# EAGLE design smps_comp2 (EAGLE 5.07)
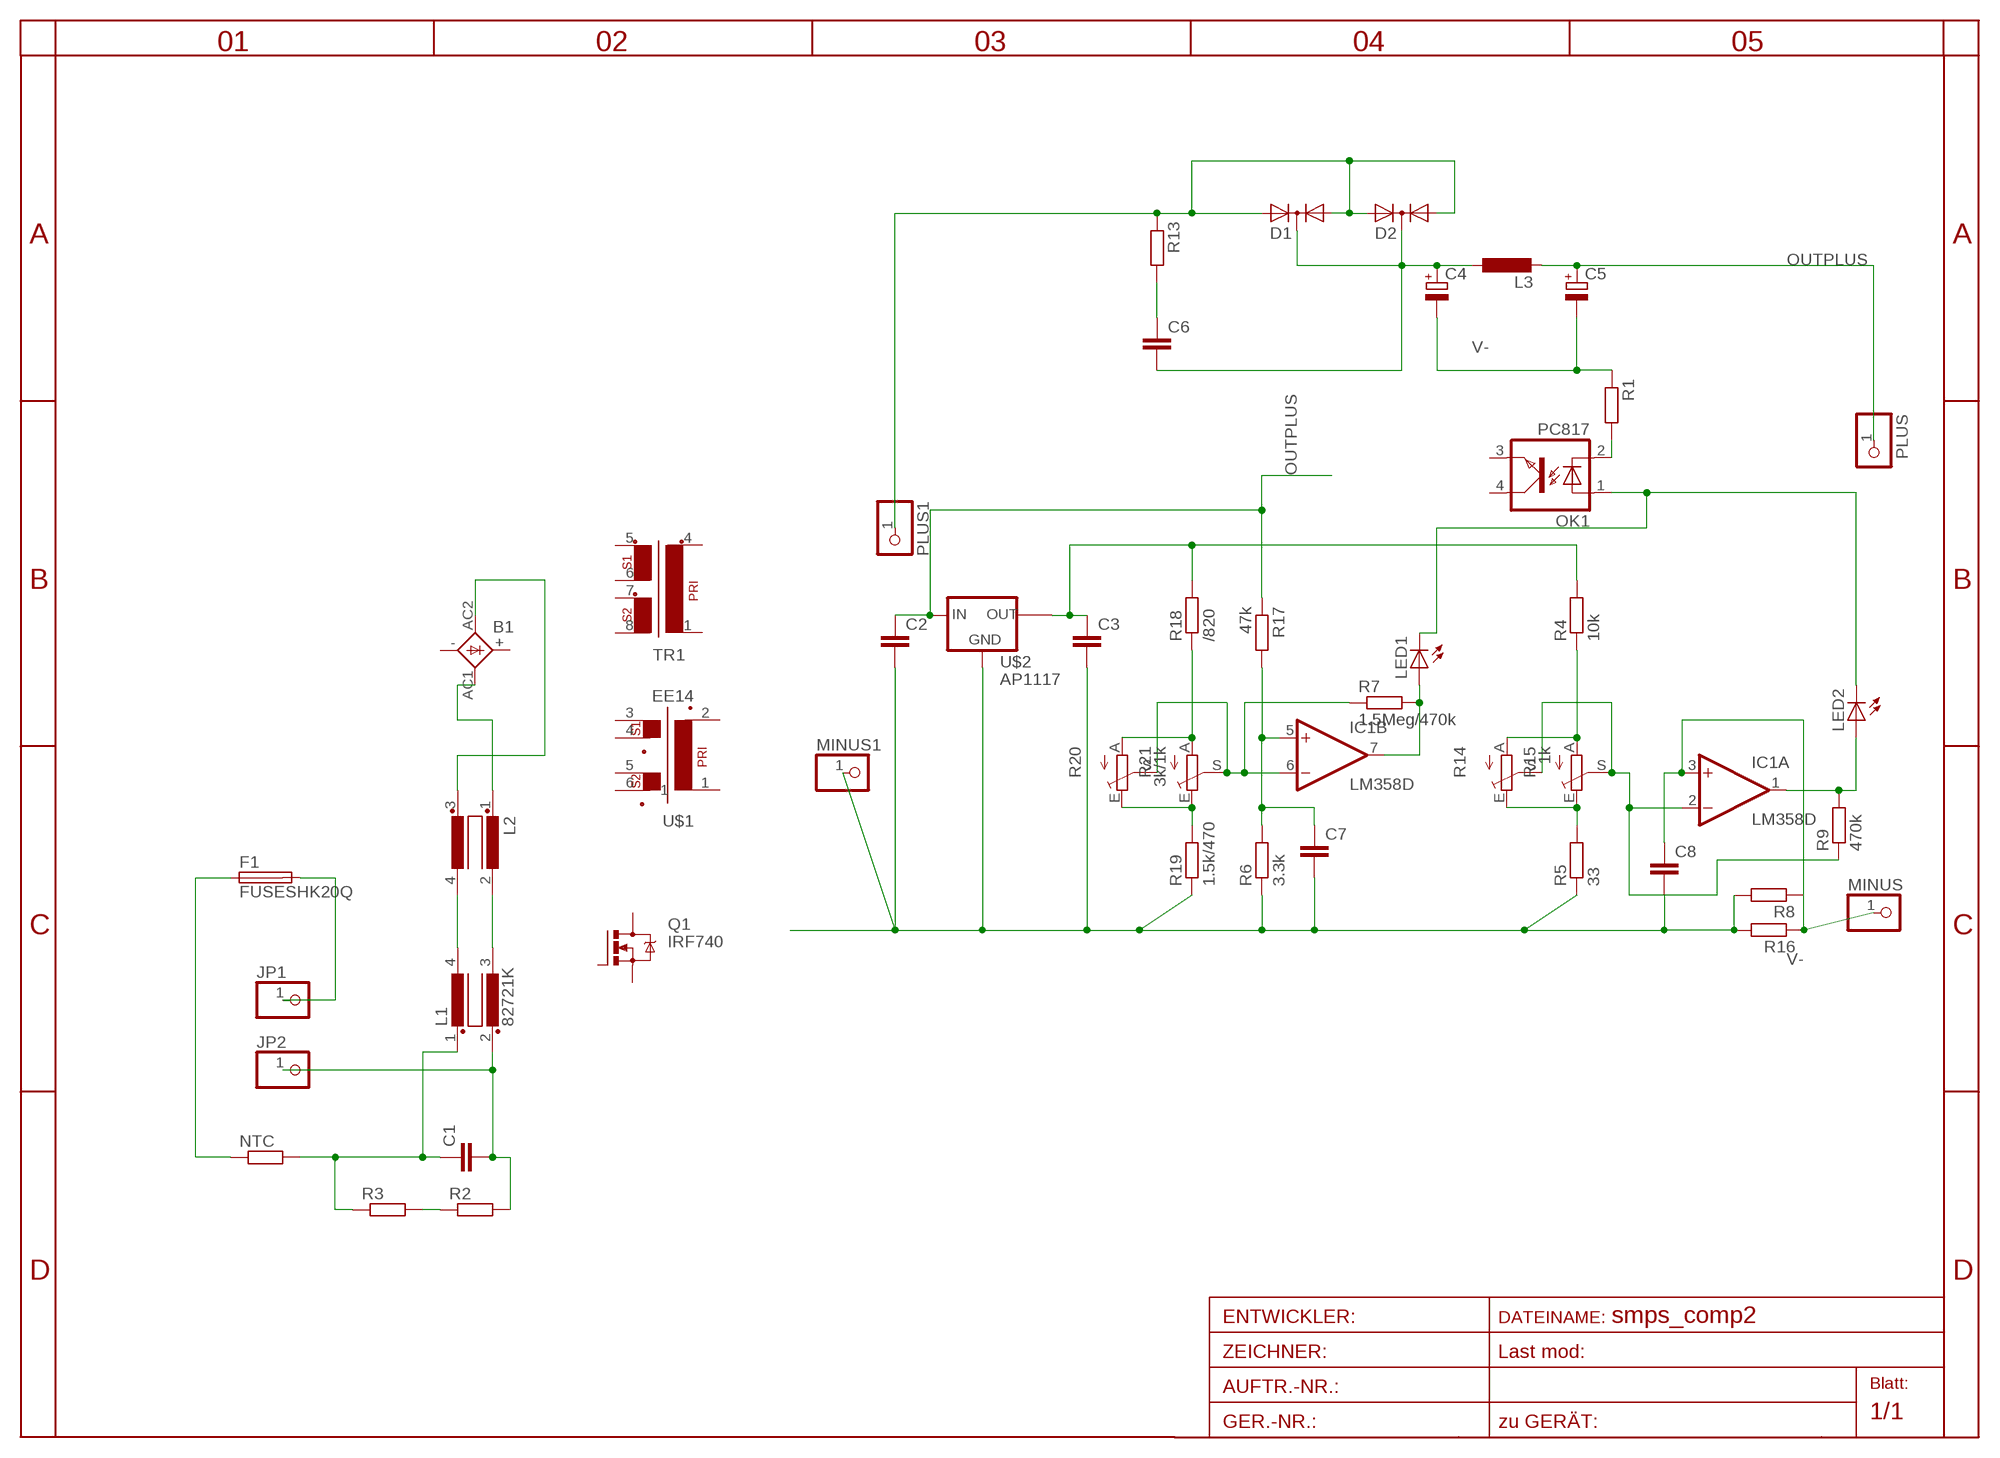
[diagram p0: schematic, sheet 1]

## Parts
B1  KBL  [KBL]
C1  C-EU150-084X183  [C150-084X183]
C2  C-EUC1206  [C1206]
C3  C-EUC1206  [C1206]
C4  CPOL-EUE5-8.5  [E5-8,5]
C5  CPOL-EUE5-8.5  [E5-8,5]
C6  C-EUC0805  [C0805]
C7  C-EUC0805  [C0805]
C8  C-EUC0805  [C0805]
D1  DIODE-2AC|CAIW220V  [IW220ABS]
D2  DIODE-2AC|CAIW220V  [IW220ABS]
F1  FUSESHK20Q  [SHK20Q]
IC1  LM358D  [SO08]
JP1  PINHD-1X12MM2  [1X2MM2]
JP2  PINHD-1X12MM2  [1X2MM2]
L1  82721K  [82721K]
L2  R1405VB1  [B1]
L3  L-EU0207/12  [0207/12]
LED1  LED3MM  [LED3MM]
LED2  LED3MM  [LED3MM]
MINUS  PINHD-1X12MM2  [1X2MM2]
MINUS1  PINHD-1X11X0.4  [1X01]
NTC  R-EU_0204/7  [0204/7]
OK1  PC817  [DIL04]
PLUS  PINHD-1X12MM2  [1X2MM2]
PLUS1  PINHD-1X11X0.4  [1X01]
Q1  IRF740  [TO220BV]
R1  R-EU_R0805  [R0805]
R2  R-EU_R1206  [R1206]
R3  R-EU_R1206  [R1206]
R4  10k  R-EU_R1206  [R1206]
R5  33  R-EU_R0805  [R0805]
R6  3.3k  R-EU_R0805  [R0805]
R7  1.5Meg/470k  R-EU_R0805  [R0805]
R8  R-EU_R2010  [R2010]
R9  470k  R-EU_R0805  [R0805]
R13  R-EU_R0805  [R0805]
R14  TRIM_EU-S64W  [S64W]
R15  1k  TRIM_EU-CA6V  [CA6V]
R16  R-EU_R2010  [R2010]
R17  47k  R-EU_R0805  [R0805]
R18  /820  R-EU_R0805  [R0805]
R19  1.5k/470  R-EU_R0805  [R0805]
R20  TRIM_EU-S64W  [S64W]
R21  3k/1k  TRIM_EU-CA6V  [CA6V]
TR1  EE20-2  [EE20-2]
U$1  EE14  [EE14]
U$2  AP1117  [SOT223]

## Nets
A: R4.1 R14.A R15.A
A1: R18.1 R20.A R21.A
CPLUS: C4.+ C6.2 D1.C D2.C L3.1
E: R5.2 R14.E R15.E
E1: R19.2 R20.E R21.E
N$1: C1.2 JP2.1 L1.2 R2.2
N$2: C1.1 L1.1 NTC.2 R3.1
N$3: F1.2A JP1.1
N$4: IC1.7(B:OUT) LED1.A R7.2
N$5: L1.4 L2.4
N$6: R2.1 R3.2
N$7: B1.AC2(AC1) L2.3
N$8: B1.AC1(AC2) L2.1
N$9: F1.1A NTC.1
N$10: IC1.6(B:-IN) R7.1 R21.S
N$11: IC1.1(A:OUT) LED2.A R9.2
N$12: OK1.2(C) R1.2
N$13: LED1.K(C) LED2.K(C) OK1.1(A)
N$14: L1.3 L2.2
N$16: C7.1 IC1.5(B:+IN) R6.2 R17.2
N$27: C6.1 R13.2
OUT: C8.1 IC1.3(A:+IN) MINUS.1 R8.1 R16.1
OUTPLUS: C2.1 C5.+ L3.2 PLUS.1 R17.1 U$2.3(IN)
S: IC1.2(A:-IN) R9.1 R14.S R15.S
S1: R20.S
TPLUS: D1.A1 D1.A2 D2.A1 D2.A2 PLUS1.1 R13.1
V+: C3.1 R4.2 R18.2 U$2.4(TAB)
V-: C2.2 C3.2 C4.- C5.- C7.2 C8.2 MINUS1.1 R1.1 R5.1 R6.1 R8.2 R16.2 R19.1 U$2.1(GND)
Unconnected: B1.+ B1.- OK1.3(EMIT) OK1.4(COL) Q1.D Q1.G Q1.S TR1.1 TR1.4 TR1.5 TR1.6 TR1.7 TR1.8 U$1.1 U$1.2 U$1.3 U$1.4 U$1.5 U$1.6 U$2.2(OUT)

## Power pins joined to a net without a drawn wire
V+: IC1.8(P:V+)
V-: IC1.4(P:V-)

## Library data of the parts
B1 = rectifier:KBL: DIOTEC RECTIFIER
C1-C3 C6-C8 = rcl:C-EU: CAPACITOR, European symbol
C4 C5 = rcl:CPOL-EU: POLARIZED CAPACITOR, European symbol
D1 D2 = diode:DIODE-2AC|CA: Dual DIODE Anode-Cathode|Cathode-Anode
F1 = fuse:FUSE: Fuse
IC1 = linear:LM358: OP AMP also LM158; LM258; LM2904 Source: http://cache.national.com/ds/LM/LM158.pdf
JP1 JP2 MINUS MINUS1 PLUS PLUS1 = pinhead:PINHD-1X1: PIN HEADER
L1 = inductors:82721K: FILTER
L2 = inductor-nkl:R1405V: Übertrager (verlustarm) bis typ. 400kHz Power transformer (low loss) up to typ. 400kHz
L3 = rcl:L-EU: INDUCTOR, European symbol
LED1 LED2 = led:LED: LED
NTC R1-R9 R13 R16-R19 = rcl:R-EU_: RESISTOR, European symbol
OK1 = optocoupler:PC817: SHARP OPTO COUPLER
Q1 = transistor-power:IRF740: N-CHANNEL MOS FET
R14 R15 R20 R21 = pot:TRIM_EU-: POTENTIOMETER
TR1 = trafo:EE20-2: TRANSFORMER 1 primary winding, 2 secondary windings ERA
U$1 = trafo:EE14
U$2 = v-reg:AP1117

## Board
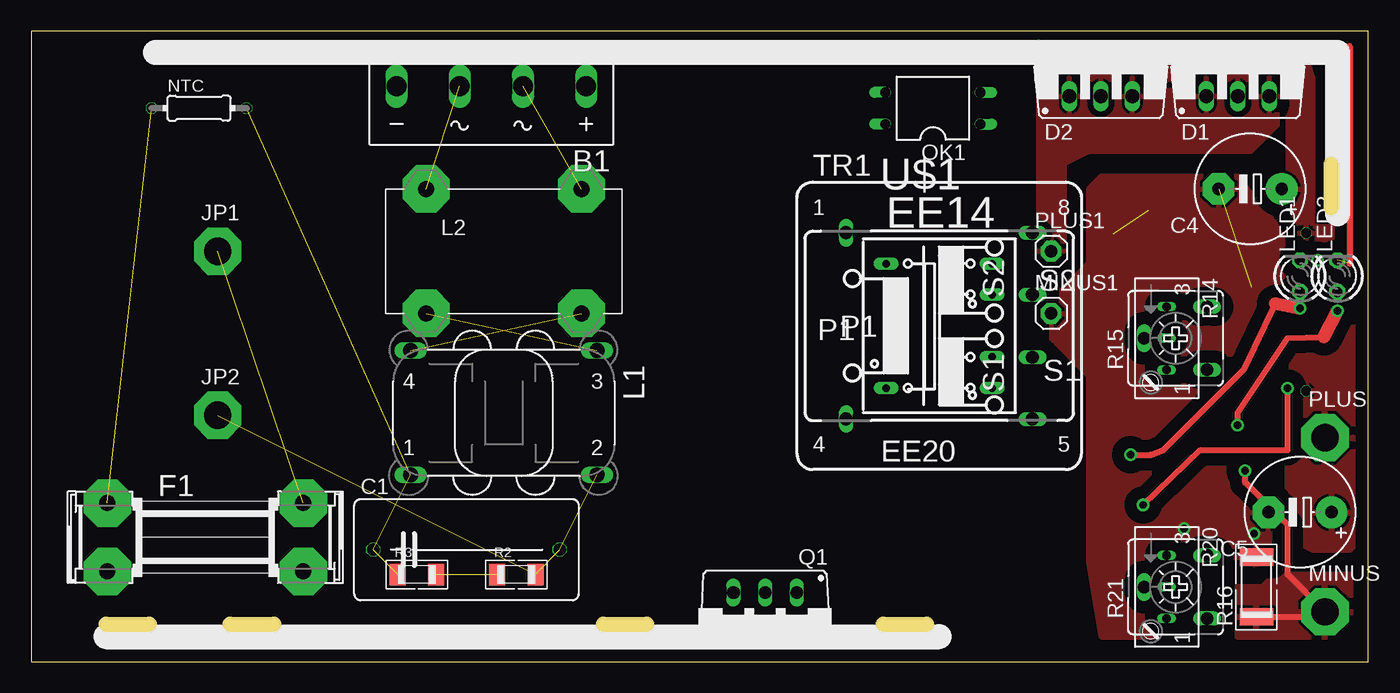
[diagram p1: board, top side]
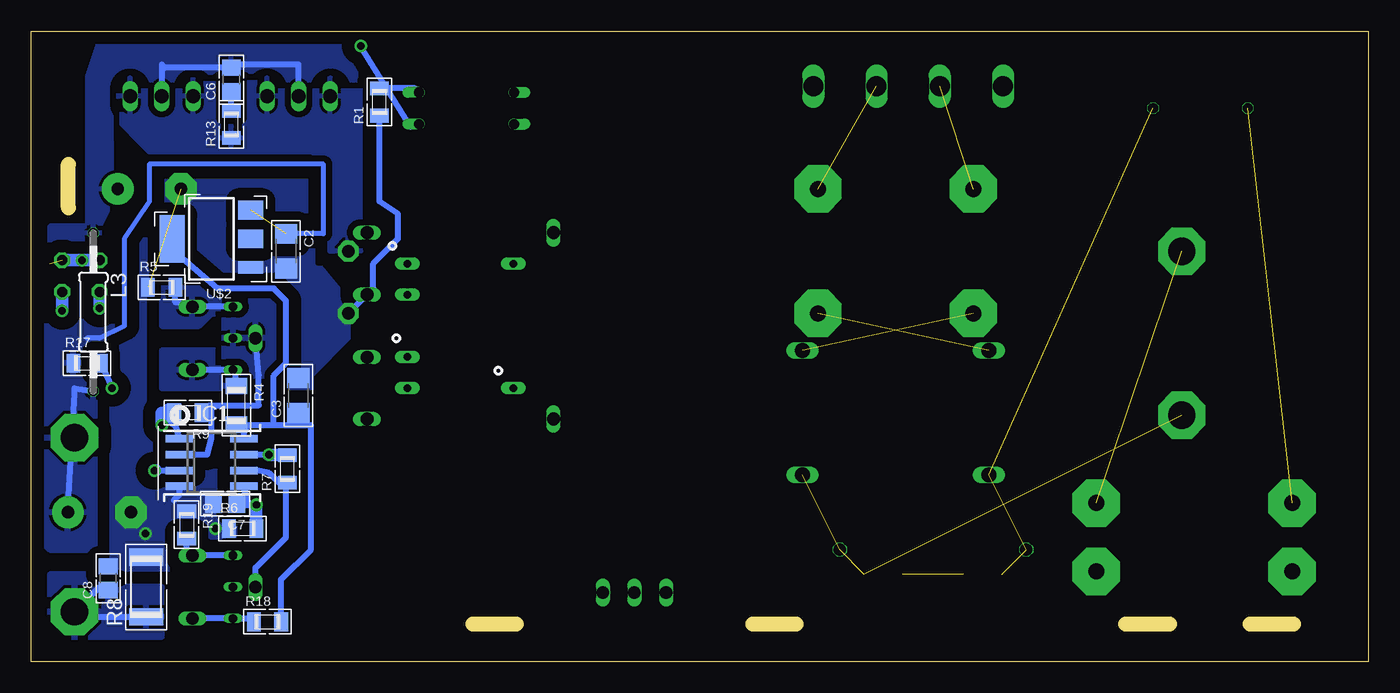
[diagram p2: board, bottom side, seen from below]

Size 107.5 x 50.7 mm. Coordinates in mm from the lower left corner, seen from the top.
Outline: 0,0 107.5,0 107.5,50.7 0,50.7 0,0
Copper layers (1*16): Top 0.035mm / dielectric 1.5mm / Bottom 0.035mm
Design rules "default": minimum track width 10mil, minimum drill 20mil, track to track 8mil, track to pad 8mil, pad to pad 8mil, via to via 8mil, smd to smd 8mil, copper to edge 40mil, drill to drill 8mil, minimum pad ring 1mil, minimum via ring 8mil, stop-mask expansion 4mil, vias tented up to drill 0mil, thermal gap 10mil
Milling: 5 lines

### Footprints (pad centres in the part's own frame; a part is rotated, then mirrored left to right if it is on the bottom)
KBL = drill 1.6 long: + -7.62,-1.27; - 7.62,-1.27; AC1 2.54,-1.27; AC2 -2.54,-1.27
C150-084X183 = drill 1.016 octagon: 1 -7.493,0; 2 7.493,0
C1206 = smd 1.6 x 1.8: 1 -1.4,0; 2 1.4,0
E5-8,5 = drill 1 pad 2.54 round: + -2.54,0 | drill 1 pad 2.54 octagon: - 2.54,0
C0805 = smd 1.3 x 1.5: 1 -0.95,0; 2 0.95,0
IW220ABS = drill 1.118 long: A1 -2.54,-2.54; A2 2.54,-2.54; C 0,-2.54
SHK20Q = drill 1.3 pad 3.81 octagon: 1A -7.874,2.75; 1B -7.874,-2.75; 2A 7.874,2.75; 2B 7.874,-2.75
SO08 = smd 0.6 x 2.2: 1 -1.905,-2.6; 2 -0.635,-2.6; 3 0.635,-2.6; 4 1.905,-2.6; 5 1.905,2.6; 6 0.635,2.6; 7 -0.635,2.6; 8 -1.905,2.6
1X2MM2 = drill 2.2 pad 3.81 octagon: 1 0,0
82721K = drill 1.194 long: 1 7.493,5.004; 2 -7.493,5.004; 3 -7.493,-5.004; 4 7.493,-5.004
B1 = drill 1.27 pad 3.81 octagon: 1 -6.25,5; 2 -6.25,-5; 3 6.25,5; 4 6.25,-5
0207/12 = drill 0.813 octagon: 1 -6.35,0; 2 6.35,0
LED3MM = drill 0.8 pad 1.27 octagon: A -1.27,0; K 1.27,0
1X01 = drill 1 pad 1.676 octagon: 1 0,0
0204/7 = drill 0.813 octagon: 1 -3.81,0; 2 3.81,0
DIL04 = drill 0.813 offset: 1 -1.27,-3.81; 2 1.27,-3.81; 3 1.27,3.81; 4 -1.27,3.81
TO220BV = drill 1.016 long: D 0,-2.54; G -2.54,-2.54; S 2.54,-2.54
R0805 = smd 1.1 x 1.5: 1 -1.1,0; 2 1.1,0
R1206 = smd 1.3 x 1.7: 1 -1.55,0; 2 1.55,0
R2010 = smd 1.4 x 2.7: 1 -2.4,0; 2 2.4,0
S64W = drill 0.7 long: A 2.54,1.27; E -2.54,1.27; S 0,1.27
CA6V = drill 1.016 long: A -2.54,-2.54; E 2.54,-2.54; S 0,2.54
EE20-2 = drill 1.016 long: 1 -7.493,7.493; 4 -7.493,-7.493; 5 7.493,-7.493; 6 7.493,-2.515; 7 7.493,2.515; 8 7.493,7.493
EE14 = drill 0.6 pad 1 long: 1 4.25,-5; 2 4.25,5; 3 -4.25,5 | drill 0.6 pad 1.016 long: 4 -4.25,2.5; 5 -4.25,-2.5; 6 -4.25,-5
SOT223 = smd 1 x 2: 1 -2.3,-3.15 | smd 1.5 x 2: 2 0,-3.15; 3 2.3,-3.15 | smd 3.8 x 2: 4 0,3.15

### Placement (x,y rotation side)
B1  37,45 180 top
C1  35,9 0 top
C2  87,33 270 bottom
C3  86,21.4 90 bottom
C4  98,38 180 top
C5  102,12 180 top
C6  91.4,46.8 90 bottom
C7  91.9,12.7 180 bottom
C8  101.3,6.7 90 bottom
D1  97,48 0 top
D2  86,48 0 top
F1  14,10 0 top
IC1  93,16 270 bottom
JP1  15,33 0 top
JP2  15,19.8 0 top
L1  38,20 180 top
L2  38,33 0 top
L3  102.5,28.1 270 bottom
LED1  102,31 90 top
LED2  105,31 90 top
MINUS  104,4 0 top
MINUS1  82,28 0 top
NTC  13.5,44.5 0 top
OK1  72.5,44.5 90 top
PLUS  104,18 0 top
PLUS1  82,33 0 top
Q1  59,3 180 top
R1  79.5,45 90 bottom
R2  39,7 0 top
R3  31,7 0 top
R4  91,20.6 270 bottom
R5  97,30.1 0 bottom
R6  90.5,10.7 0 bottom
R7  86.9,15.5 90 bottom
R8  98.25,6 90 bottom
R9  94.9,20 180 bottom
R13  91.4,43.2 90 bottom
R14  90,26 270 top
R15  92,26 90 top
R16  98.5,6 90 top
R17  103,24 0 bottom
R18  88.5,3.2 0 bottom
R19  95,11 270 bottom
R20  90,6 270 top
R21  92,6 90 top
TR1  73,27 0 top
U$1  73,27 180 top
U$2  93,34 90 bottom

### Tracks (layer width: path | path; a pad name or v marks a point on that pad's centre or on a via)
A
  Bottom 0.5: R4.1 91.1,23.29 R14.A R15.A
  pour Bottom (isolate 0.5, rank 2): 92,25 97,25 97,24 97,22 92,22
A1
  Bottom 0.5: R21.A R20.A 89.86,3.46 R18.1
CPLUS
  Bottom 0.5: D2.C 86,48 91.15,48 C6.2 96.75,47.75 97,48 D1.C
  pour Bottom (isolate 1): 81,50 102,50 103,47 103,35 106,35 106,32 103,32 102,33 102,35 101,37 101.1,46.8 81.1,46.8
  pour Top (isolate 1): 81,50 102,50 103,47 103,35 106,35 106,32 103,32 102,33 102,35 101,37 101.1,46.8 81.1,46.8
E
  Bottom 0.5: R5.2 95.9,28.9 R15.E R14.E
  pour Bottom (isolate 0.5, rank 2): 93,28 92,28 92,30 97,30 97,27 94,27
E1
  Bottom 0.5: R19.2 95,8.9 R21.E R20.E
N$1  (3 unrouted)
N$2  (3 unrouted)
N$3  (1 unrouted)
N$4  (via drill 0.6)
  Top 0.5: v88.4,16.64 90,16.64 91,17 97.5,23.5 100,28.8
  Top 1: 100,28.8 v102,28.4
  Bottom 0.5: v88.4,16.64 IC1.7
  Bottom 1: v102,28.4 LED1.A | R7.2 v88.4,16.64
N$5  (1 unrouted)
N$6  (1 unrouted)
N$7  (1 unrouted)
N$8  (1 unrouted)
N$9  (1 unrouted)
N$10
  Bottom 0.5: R21.S 89.46,7.54 87,10 87,14.4 | IC1.6 89.36,15.37 88.36,15.16 87.6,14.4 87,14.4 | 87,14.4 R7.1
N$11  (via drill 0.6)
  Top 0.5: 103.9,26.1 101,26 97,20 v97,19
  Top 1: 103.9,26.1 v105,28.2
  Bottom 0.5: 97,20 96.6,20.5 R9.2 | 96,19.3 IC1.1
  Bottom 1: v105,28.2 LED2.A | 97,20 v97,19 | R9.2 96,19.3
N$12
  Bottom 0.5: R1.2 76.64,46.1 OK1.2
N$13  (via drill 0.6)  (1 unrouted)
  Top 0.5: v81,49.5 106,49.5 106,32
  Bottom 0.5: v81,49.5 77,43 OK1.1
  Bottom 1: LED1.K v103.4,32.27 LED2.K
N$14  (1 unrouted)
N$16  (via drill 0.6)
  Top 0.5: v89.4,12.6 94,17 101,17 v101,22
  Bottom 0.5: 102,24 R17.2 v101,22 | IC1.5 90,12.7 v89.4,12.6 90.5,12.5 C7.1
  Bottom 1: R6.2 v89.4,12.6
N$27
  Bottom 0.5: R13.2 C6.1
OUT  (via drill 0.6)
  Top 0.5: R16.1 103.6,3.6 MINUS.1 101,7 101,11 97.6,14.4 v97.6,15.37 | R16.1 98.8,3.6 | 98,4 99.6,4 R16.1
  Bottom 0.5: C8.1 101.25,5.75 101,6 102,6 MINUS.1 103.6,3.6 R8.1 | 97.47,15.37 IC1.3
  Bottom 1: v97.6,15.37 97.47,15.37
  pour Bottom (isolate 1.016, rank 3): 102,6 103,7 106,7 106,2 97,2 97,6
  pour Top (isolate 1.016, rank 3): 100,7 106,7 106,2 97,2 97,6 99,6
OUTPLUS  (1 unrouted)
  Bottom 0.406: C2.1 84,34.4 84,40 98,40 98,37 100,34 100,27 102,26 103,26
  Bottom 0.5: L3.2 103.95,21.95 104,22 104,21.54 C5.+
  pour Bottom (isolate 1, rank 5): 107,28 107,10 106,9 103,9 101,10 101,28
  pour Top (isolate 1, rank 5): 107,28 107,10 106,9 103,9 101,10 101,28
S
  Bottom 0.5: IC1.2 93.36,16.64 93,18 93,20.6 | 93,20.6 89.2,20.6 89.2,23.04 R15.S | R9.1 93.5,20.5 93,20.6
  pour Bottom (isolate 0.5): 88,29 92,29 92,23 88,23
TPLUS
  pour Bottom (isolate 0.5, rank 2): 81,33 81,46 82,47 100,47 101,46 101,44 98,41 85,41 83.5,40 83.5,33
  pour Top (isolate 0.5, rank 2): 81,33 81,46 82,47 100,47 101,46 101,44 98,41 85,41 83,40 83,33
V+
  Bottom 0.5: R18.2 87.4,6.6 85,9 85,19 86,19 | U$2.4 96.15,33.15 92.5,30 88,30 87,29 87,24 88,23 88,19 | 86,19 88,19 | 86,19 C3.1 | 88,19 90,19 | 90,19 90.95,19 R4.2 | IC1.8 90.4,18.6 90,19
V-  (via drill 0.6)  (1 unrouted)
  Bottom 0.5: IC1.4 95.6,13.4 96,13 | R1.1 79.5,37 78,36 78,34 80,32 80,30 MINUS1.1
  other vias: 98.3,10.3 92.7,10.7
  pour Bottom (isolate 1, rank 4, no thermals): 97,40 86,40 84.5,38 84.5,32 82,29 82,26 85,23 85,8 86,2 101,2 101,34
  pour Top (isolate 1, rank 4): 97,39 86,39 85,38 85,32 82,29 82,26 85,23 85,8 86,2 101,2 101,5 101,34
